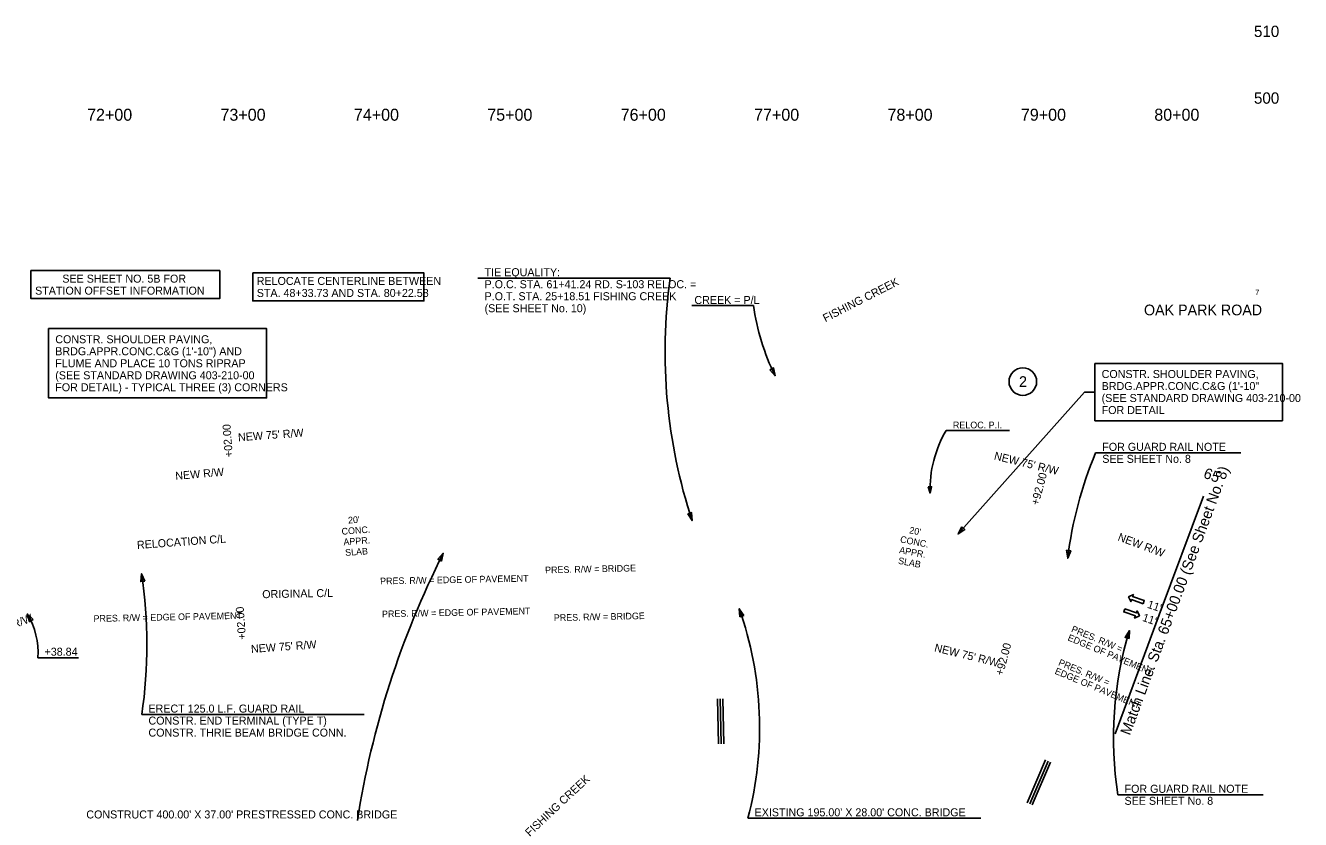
# Model space of a CAD drawing. Extents: x 1964377 to 1966966, y 1116414 to 1123213.
# Drawn here: x 1966010 to 1966966, y 1118190 to 1118785 of the extents above; entities that cross this region are included whole.
import ezdxf

# ---------------------------------------------------------------- set-up
doc = ezdxf.new("R2010")
doc.units = 0
for name, color, linetype in [('RD_DDB_Profile_Elev', 7, 'Continuous'), ('RD_DDB_StaTX', 7, 'Continuous'), ('RD_EX_Bridge', 7, 'Continuous'), ('RD_EX_DV_TX_Prop', 7, 'Continuous'), ('RD_EX_RW_TX', 7, 'Continuous'), ('RD_HC_Data', 7, 'Continuous'), ('RD_HC_Data_Rel', 7, 'Continuous'), ('RD_HC_TX_Rel_Sta50', 7, 'Continuous'), ('RD_PD_Bridge', 7, 'Continuous'), ('RD_PD_Final_LnLine', 7, 'Continuous'), ('RD_PD_Final_TX', 7, 'Continuous'), ('RD_PD_RW_TX', 7, 'Continuous'), ('RD_SHT_MatchLine', 7, 'Continuous'), ('RD_SHT_TX', 7, 'Continuous'), ('RD_TX_Misc1', 7, 'Continuous'), ('RD_TX_RoadID', 7, 'Continuous'), ('RD_TX_StaOff', 7, 'Continuous')]:
    doc.layers.add(name, color=color, linetype=linetype)

msp = doc.modelspace()

# ---------------------------------------------------------------- linework, layer by layer
at = {"layer": 'RD_EX_Bridge'}
msp.add_line((1966726.55, 1118191.15), (1966552, 1118191.15), dxfattribs=at)
msp.add_lwpolyline([(1966548.92, 1118343.22), (1966545.54, 1118348.18), (1966545.99, 1118342.2)], close=True, dxfattribs=at)
msp.add_arc((1966291.3, 1118259.06), 269.41, 345.3987, 19.31617, dxfattribs=at)
at = {"layer": 'RD_EX_DV_TX_Prop'}
msp.add_line((1966556.21, 1118575.66), (1966509.9, 1118575.66), dxfattribs=at)
msp.add_lwpolyline([(1966568.41, 1118527.44), (1966572.36, 1118522.92), (1966571.19, 1118528.81)], close=True, dxfattribs=at)
msp.add_circle((1966758.07, 1118518.52), 10.35, dxfattribs=at)
msp.add_arc((1966728.05, 1118599.43), 173.48, 187.87332, 206.16861, dxfattribs=at)
at = {"layer": 'RD_HC_Data'}
for p, q in [((1966493.72, 1118596), (1966349.58, 1118596)), ((1966529.92, 1118246.96), (1966529.28, 1118280.71)), ((1966531.92, 1118246.99), (1966531.28, 1118280.75)), ((1966533.92, 1118247.03), (1966533.28, 1118280.79)), ((1966761.43, 1118202.87), (1966775.13, 1118234.87)), ((1966763.27, 1118202.09), (1966776.96, 1118234.08)), ((1966765.11, 1118201.3), (1966778.8, 1118233.29))]:
    msp.add_line(p, q, dxfattribs=at)
msp.add_lwpolyline([(1966506.86, 1118419.35), (1966510.15, 1118414.34), (1966509.81, 1118420.33)], close=True, dxfattribs=at)
msp.add_arc((1966893.41, 1118540.56), 403.52, 172.10349, 198.22863, dxfattribs=at)
at = {"layer": 'RD_HC_Data_Rel'}
msp.add_line((1966748.12, 1118481.96), (1966700.68, 1118481.96), dxfattribs=at)
for points in [[(1966180.8, 1118599.95), (1966309.11, 1118599.95), (1966309.11, 1118578.95), (1966180.8, 1118578.95)], [(1966687.1, 1118439.67), (1966688.52, 1118434.87), (1966689.69, 1118439.73)]]:
    msp.add_lwpolyline(points, close=True, dxfattribs=at)
msp.add_arc((1966776.97, 1118437.15), 88.48, 149.57407, 181.47482, dxfattribs=at)
at = {"layer": 'RD_PD_Bridge'}
for points in [[(1966027.77, 1118558.24), (1966191.21, 1118558.24), (1966191.21, 1118506.24), (1966027.77, 1118506.24)], [(1966812.17, 1118532.18), (1966952.66, 1118532.18), (1966952.66, 1118489.18), (1966812.17, 1118489.18)], [(1966712.27, 1118409.63), (1966709.58, 1118404.27), (1966714.59, 1118407.56)], [(1966322.37, 1118383.89), (1966323.59, 1118389.77), (1966319.59, 1118385.29)]]:
    msp.add_lwpolyline(points, close=True, dxfattribs=at)
msp.add_lwpolyline([(1966812.17, 1118510.68), (1966804.39, 1118510.68), (1966709.58, 1118404.27)], dxfattribs=at)
msp.add_arc((1966927.97, 1118084.95), 676.89, 153.2361, 171.11064, dxfattribs=at)
at = {"layer": 'RD_PD_Final_LnLine'}
for points in [[(1966848.26, 1118352.04), (1966849.06, 1118354.31), (1966840.4, 1118357.34), (1966840.94, 1118358.88), (1966837.33, 1118357.14), (1966839.07, 1118353.54), (1966839.61, 1118355.08)], [(1966834.57, 1118348.11), (1966833.78, 1118345.84), (1966842.44, 1118342.81), (1966841.9, 1118341.28), (1966845.5, 1118343.01), (1966843.77, 1118346.62), (1966843.23, 1118345.08)]]:
    msp.add_lwpolyline(points, close=True, dxfattribs=at)
at = {"layer": 'RD_PD_RW_TX'}
msp.add_line((1966050.07, 1118311.53), (1966019.7, 1118311.53), dxfattribs=at)
msp.add_lwpolyline([(1966016.1, 1118340.19), (1966011.79, 1118344.36), (1966013.44, 1118338.59)], close=True, dxfattribs=at)
msp.add_arc((1965963.33, 1118315.31), 56.5, 356.1639, 30.94324, dxfattribs=at)
at = {"layer": 'RD_SHT_MatchLine'}
msp.add_lwpolyline([(1966827.25, 1118254.5), (1966860.36, 1118343.55), (1966893.46, 1118432.59)], dxfattribs=at)
at = {"layer": 'RD_TX_Misc1'}
for p, q in [((1966921.55, 1118465.1), (1966812.62, 1118465.1)), ((1966264.23, 1118268.9), (1966097.62, 1118268.9)), ((1966938.24, 1118208.77), (1966829.31, 1118208.77))]:
    msp.add_line(p, q, dxfattribs=at)
for points in [[(1966790.91, 1118392.06), (1966791.76, 1118386.12), (1966794, 1118391.69)], [(1966099.87, 1118369.01), (1966097.48, 1118374.52), (1966096.8, 1118368.55)], [(1966837.76, 1118325.87), (1966837.96, 1118331.87), (1966834.79, 1118326.77)]]:
    msp.add_lwpolyline(points, close=True, dxfattribs=at)
for centre, radius, start, end in [((1967085.93, 1118350.68), 296.29, 157.28358, 173.12947), ((1965737.9, 1118321.23), 363.51, 351.72258, 8.42854), ((1967103.78, 1118251.34), 277.76, 163.14545, 188.81602)]:
    msp.add_arc(centre, radius, start, end, dxfattribs=at)
at = {"layer": 'RD_TX_StaOff'}
msp.add_lwpolyline([(1966014.56, 1118601.68), (1966156.11, 1118601.68), (1966156.11, 1118580.68), (1966014.56, 1118580.68)], close=True, dxfattribs=at)

# ---------------------------------------------------------------- texts
at = {"layer": 'RD_DDB_Profile_Elev'}
for s, p in [('510', (1966931.34, 1118776.8)), ('500', (1966931.34, 1118726.8))]:
    msp.add_text(s, height=8.5, dxfattribs=at).set_placement(p)
at = {"layer": 'RD_DDB_StaTX'}
for s, p in [('72+00', (1966056.62, 1118714.05)), ('73+00', (1966156.62, 1118714.05)), ('74+00', (1966256.62, 1118714.05)), ('75+00', (1966356.62, 1118714.05)), ('76+00', (1966456.62, 1118714.05)), ('77+00', (1966556.62, 1118714.05)), ('78+00', (1966656.62, 1118714.05)), ('79+00', (1966756.62, 1118714.05)), ('80+00', (1966856.62, 1118714.05))]:
    msp.add_text(s, height=9, dxfattribs=at).set_placement(p)
at = {"layer": 'RD_EX_Bridge'}
msp.add_text("EXISTING 195.00' X 28.00' CONC. BRIDGE", height=6, dxfattribs=at).set_placement((1966557, 1118192.65))
at = {"layer": 'RD_EX_DV_TX_Prop'}
for s, height, p in [('CREEK = P/L', 6, (1966511.9, 1118576.66)), ('2', 8, (1966755.23, 1118514.53))]:
    msp.add_text(s, height=height, dxfattribs=at).set_placement(p)
at = {"layer": 'RD_EX_RW_TX'}
for s, rotation, p in [('PRES. R/W = BRIDGE', 1.29481, (1966400, 1118374.73)), ('PRES. R/W = EDGE OF PAVEMENT', 1.09247, (1966276.33, 1118366.46)), ('PRES. R/W = EDGE OF PAVEMENT', 1.18264, (1966277.75, 1118341.8)), ('PRES. R/W = EDGE OF PAVEMENT', 1.18264, (1966061.5, 1118338.36)), ('PRES. R/W = BRIDGE', 1.29481, (1966406.56, 1118338.95)), ('EDGE OF PAVEMENT', 337.30763, (1966791.26, 1118324.72)), ('PRES. R/W = ', 337.30763, (1966793.96, 1118331.18)), ('PRES. R/W = ', 337.30763, (1966784.29, 1118306.11)), ('EDGE OF PAVEMENT', 337.30763, (1966781.59, 1118299.66))]:
    msp.add_text(s, height=5, rotation=rotation, dxfattribs=at).set_placement(p)
at = {"layer": 'RD_HC_Data'}
for s, p in [('TIE EQUALITY:', (1966354.58, 1118597.5)), ('P.O.C. STA. 61+41.24 RD. S-103 RELOC. =', (1966354.58, 1118588.5)), ('P.O.T. STA. 25+18.51 FISHING CREEK', (1966354.58, 1118579.5)), ('(SEE SHEET No. 10)', (1966354.58, 1118570.5))]:
    msp.add_text(s, height=6, dxfattribs=at).set_placement(p)
at = {"layer": 'RD_HC_Data_Rel'}
for s, height, p in [('RELOCATE CENTERLINE BETWEEN', 6, (1966183.8, 1118590.95)), ('STA. 48+33.73 AND STA. 80+22.58', 6, (1966183.8, 1118581.95)), ('RELOC. P.I.', 5, (1966705.68, 1118483.46))]:
    msp.add_text(s, height=height, dxfattribs=at).set_placement(p)
msp.add_text('RELOCATION C/L', height=6, rotation=4.14297, dxfattribs=at).set_placement((1966094.21, 1118393.02))
at = {"layer": 'RD_HC_TX_Rel_Sta50'}
msp.add_text('65', height=8, rotation=339.60388, dxfattribs=at).set_placement((1966892.87, 1118446.68))
at = {"layer": 'RD_PD_Bridge'}
for s, p in [('CONSTR. SHOULDER PAVING,', (1966032.77, 1118547.24)), ('BRDG.APPR.CONC.C&G (1\'-10") AND', (1966032.77, 1118538.24)), ('FLUME AND PLACE 10 TONS RIPRAP', (1966032.77, 1118529.24)), ('(SEE STANDARD DRAWING 403-210-00', (1966032.77, 1118520.24)), ('CONSTR. SHOULDER PAVING,', (1966817.17, 1118521.18)), ('BRDG.APPR.CONC.C&G (1\'-10"', (1966817.17, 1118512.18)), ('FOR DETAIL) - TYPICAL THREE (3) CORNERS', (1966032.77, 1118511.24)), ('(SEE STANDARD DRAWING 403-210-00', (1966817.17, 1118503.18)), ('FOR DETAIL', (1966817.17, 1118494.18)), ("CONSTRUCT 400.00' X 37.00' PRESTRESSED CONC. BRIDGE", (1966056.04, 1118191.05))]:
    msp.add_text(s, height=6, dxfattribs=at).set_placement(p)
at = {"layer": 'RD_PD_Final_TX'}
for s, height, rotation, p in [("20'", 5, 4.14297, (1966252.42, 1118412.05)), ('CONC.', 5, 4.14297, (1966247.58, 1118403.68)), ("20'", 5, 349.25388, (1966672.64, 1118404.84)), ('APPR.', 5, 4.14297, (1966248.97, 1118395.76)), ('SLAB', 5, 4.14297, (1966250.24, 1118387.83)), ('APPR.', 5, 349.25388, (1966665.12, 1118389.98)), ('CONC.', 5, 349.25388, (1966665.81, 1118398)), ('SLAB', 5, 349.25388, (1966664.31, 1118381.99)), ("11'", 6, 341.4002, (1966850.93, 1118349.1)), ("11'", 6, 341.4002, (1966847.19, 1118339.22))]:
    msp.add_text(s, height=height, rotation=rotation, dxfattribs=at).set_placement(p)
at = {"layer": 'RD_PD_RW_TX'}
for s, rotation, p in [('+02.00', 94.14297, (1966165.86, 1118462.12)), ("NEW 75' R/W", 4.14297, (1966169.95, 1118473.76)), ("NEW 75' R/W", 346.19669, (1966736.13, 1118460.23)), ('NEW R/W', 4.9386, (1966122.99, 1118444.79)), ('+92.00', 75.00388, (1966769.85, 1118425.42)), ('NEW R/W', 339.42498, (1966828.79, 1118399.66)), ('+02.00', 94.14297, (1966175.78, 1118325.26)), ('NEW R/W', 21.11702, (1965982.38, 1118325.87)), ("NEW 75' R/W", 4.14297, (1966179.67, 1118315.1)), ("NEW 75' R/W", 346.19669, (1966691.35, 1118316.42)), ('+92.00', 75.00388, (1966743.11, 1118297.74))]:
    msp.add_text(s, height=6, rotation=rotation, dxfattribs=at).set_placement(p)
msp.add_text('+38.84', height=6, dxfattribs=at).set_placement((1966024.7, 1118313.03))
at = {"layer": 'RD_SHT_MatchLine'}
msp.add_text('Match Line: Sta. 65+00.00 (See Sheet No. 8)', height=8, rotation=69.60388, dxfattribs=at).set_placement((1966838.38, 1118252.87))
at = {"layer": 'RD_SHT_TX'}
for s, height, p in [('7', 4, (1966932.23, 1118583.35)), ('OAK PARK ROAD', 8, (1966848.89, 1118568.2))]:
    msp.add_text(s, height=height, dxfattribs=at).set_placement(p)
at = {"layer": 'RD_TX_Misc1'}
for s, p in [('FOR GUARD RAIL NOTE', (1966817.62, 1118466.6)), ('SEE SHEET No. 8', (1966817.62, 1118457.6)), ('ERECT 125.0 L.F. GUARD RAIL', (1966102.62, 1118270.4)), ('CONSTR. END TERMINAL (TYPE T)', (1966102.62, 1118261.4)), ('CONSTR. THRIE BEAM BRIDGE CONN.', (1966102.62, 1118252.4)), ('FOR GUARD RAIL NOTE', (1966834.31, 1118210.27)), ('SEE SHEET No. 8', (1966834.31, 1118201.27))]:
    msp.add_text(s, height=6, dxfattribs=at).set_placement(p)
at = {"layer": 'RD_TX_RoadID'}
for s, rotation, p in [('FISHING CREEK', 27.05178, (1966610.1, 1118562.94)), ('ORIGINAL C/L', 1.09247, (1966187.98, 1118356.12)), ('FISHING CREEK', 43.08432, (1966388.37, 1118177.16))]:
    msp.add_text(s, height=6, rotation=rotation, dxfattribs=at).set_placement(p)
at = {"layer": 'RD_TX_StaOff'}
for s, p in [('SEE SHEET NO. 5B FOR', (1966038.06, 1118592.68)), ('STATION OFFSET INFORMATION', (1966017.65, 1118583.68))]:
    msp.add_text(s, height=6, dxfattribs=at).set_placement(p)

doc.saveas('drawing.dxf')
